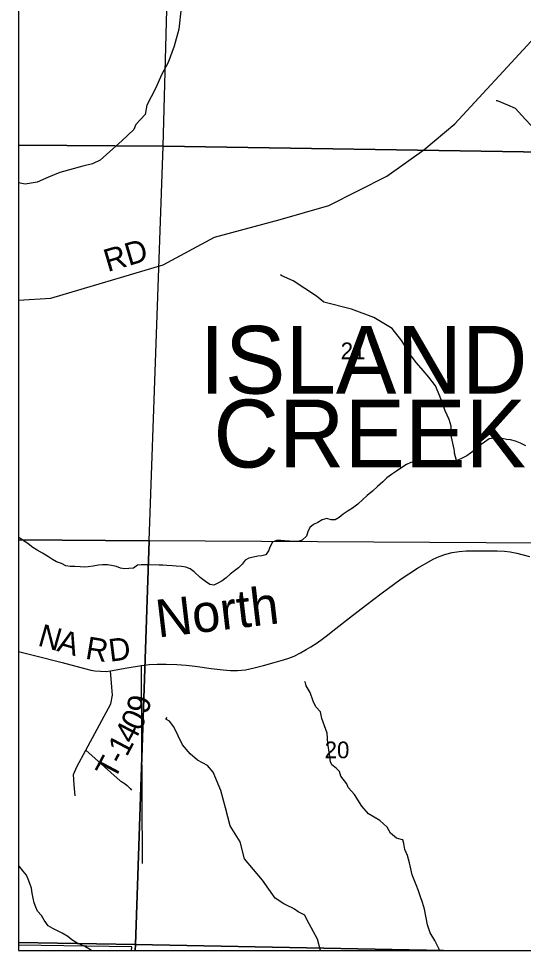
# Model space of a CAD drawing. Extents: x 2.1 to 8.9, y 14.1 to 20.9.
# Drawn here: x 2.1 to 3.368, y 14.1 to 16.441 of the extents above; entities that cross this region are included whole.
import ezdxf

# ---------------------------------------------------------------- set-up
doc = ezdxf.new("R2010")
doc.units = 0
for name, color, linetype in [('Default', 7, 'Continuous'), ('GM_X_City_Street', 7, 'Continuous'), ('GM_X_County_Road_Text', 7, 'Continuous'), ('GM_X_Interchange_Ramps', 7, 'Continuous'), ('GM_X_Minor_River', 7, 'Continuous'), ('GM_X_Minor_River_Text', 7, 'Continuous'), ('GM_X_State_Shield', 7, 'Continuous'), ('GM_X_Township_Road_Text', 7, 'Continuous'), ('PV_P_Text', 7, 'Continuous'), ('SH_Cut_Line', 7, 'Continuous'), ('SH_Data', 7, 'Continuous'), ('TX_P_Misc', 7, 'Continuous')]:
    doc.layers.add(name, color=color, linetype=linetype)

msp = doc.modelspace()

# ---------------------------------------------------------------- linework, layer by layer
at = {"layer": 'Default'}
for p, q in [((2.1, 19.1502), (2.1, 14.1)), ((2.1, 17.1299), (2.1, 16.1234)), ((2.4631, 16.1204), (2.4891, 17.1265)), ((2.1, 16.1234), (2.4631, 16.1204)), ((2.1, 16.1234), (2.1, 15.1312)), ((2.4631, 16.1204), (2.1, 16.1234)), ((2.428, 15.1288), (2.4631, 16.1204)), ((2.1, 15.1312), (2.428, 15.1288)), ((2.1, 15.1312), (2.1, 14.1197)), ((2.428, 15.1288), (2.1, 15.1312)), ((2.3934, 14.1146), (2.428, 15.1288)), ((2.428, 15.1288), (2.3934, 14.1146)), ((3.4148, 15.1232), (2.428, 15.1288)), ((2.1, 14.1197), (2.3934, 14.1146)), ((2.1, 14.1197), (2.1, 14.1)), ((2.3934, 14.1146), (2.1, 14.1197)), ((2.1, 14.1134), (2.1, 14.1)), ((2.384, 14.1091), (2.1, 14.1134)), ((2.1, 14.1), (2.3928, 14.1)), ((2.1, 14.1), (2.3837, 14.1)), ((2.1, 14.1), (6.7017, 14.1)), ((2.3837, 14.1), (2.384, 14.1091)), ((2.3928, 14.1), (2.3934, 14.1146)), ((2.3934, 14.1146), (2.3928, 14.1)), ((2.3928, 14.1), (3.167, 14.1)), ((2.3934, 14.1146), (3.167, 14.1)), ((3.167, 14.1), (2.3934, 14.1146)), ((3.167, 14.1), (3.3681, 14.1))]:
    msp.add_line(p, q, dxfattribs=at)
at = {"layer": 'GM_X_City_Street'}
for p, q in [((2.3337, 14.7617), (2.331, 14.8021)), ((2.4112, 14.3179), (2.4084, 14.8159)), ((2.3361, 14.7414), (2.3337, 14.7617)), ((2.3314, 14.7196), (2.3361, 14.7414)), ((2.269, 14.6027), (2.3314, 14.7196)), ((2.2464, 14.5614), (2.269, 14.6027)), ((2.269, 14.6027), (2.3548, 14.526)), ((2.2379, 14.5419), (2.2464, 14.5614)), ((2.2394, 14.5162), (2.2379, 14.5419)), ((2.2418, 14.4881), (2.2394, 14.5162)), ((2.3548, 14.526), (2.3587, 14.5239)), ((2.3587, 14.5239), (2.3633, 14.5211)), ((2.3633, 14.5211), (2.3677, 14.518)), ((2.3677, 14.518), (2.3723, 14.5144)), ((2.3723, 14.5144), (2.3766, 14.5104)), ((2.3766, 14.5104), (2.3801, 14.5067)), ((2.3801, 14.5067), (2.3836, 14.5026))]:
    msp.add_line(p, q, dxfattribs=at)
at = {"layer": 'GM_X_Interchange_Ramps'}
for p, q in [((2.4631, 16.1204), (2.4891, 17.1265)), ((2.428, 15.1288), (2.4631, 16.1204)), ((3.4577, 16.1051), (2.4631, 16.1204)), ((2.4631, 16.1204), (3.4577, 16.1051)), ((3.4148, 15.1232), (2.428, 15.1288))]:
    msp.add_line(p, q, dxfattribs=at)
at = {"layer": 'GM_X_State_Shield'}
for p, q in [((3.1953, 16.1767), (3.387, 16.3849)), ((3.1174, 16.1114), (3.1953, 16.1767)), ((3.0247, 16.045), (3.1174, 16.1114)), ((2.8794, 15.9713), (3.0247, 16.045)), ((2.7567, 15.9362), (2.8794, 15.9713)), ((2.5919, 15.8922), (2.7567, 15.9362)), ((2.4632, 15.8222), (2.5919, 15.8922)), ((2.1809, 15.7386), (2.4632, 15.8222)), ((2.1, 15.7337), (2.1809, 15.7386)), ((3.1889, 15.0996), (3.2067, 15.1022)), ((3.2067, 15.1022), (3.2243, 15.1035)), ((3.2243, 15.1035), (3.2648, 15.104)), ((3.2648, 15.104), (3.302, 15.1035)), ((3.302, 15.1035), (3.3198, 15.1028)), ((3.3198, 15.1028), (3.3345, 15.1014)), ((3.3345, 15.1014), (3.3509, 15.0983)), ((3.1017, 15.0601), (3.1412, 15.0827)), ((3.1412, 15.0827), (3.1564, 15.09)), ((3.1564, 15.09), (3.1732, 15.0957)), ((3.1732, 15.0957), (3.1889, 15.0996)), ((3.3509, 15.0983), (3.383, 15.0898)), ((3.0609, 15.0334), (3.1017, 15.0601)), ((3.0096, 14.9958), (3.0609, 15.0334)), ((2.9744, 14.9692), (3.0096, 14.9958)), ((2.9381, 14.9413), (2.9744, 14.9692)), ((2.8893, 14.9028), (2.9381, 14.9413)), ((2.8622, 14.882), (2.8759, 14.8919)), ((2.8759, 14.8919), (2.8893, 14.9028)), ((2.8337, 14.8626), (2.8496, 14.8729)), ((2.8496, 14.8729), (2.8622, 14.882)), ((2.1, 14.8512), (2.1395, 14.8412)), ((2.7918, 14.8395), (2.8075, 14.8472)), ((2.8075, 14.8472), (2.8224, 14.8556)), ((2.8224, 14.8556), (2.8337, 14.8626)), ((2.1395, 14.8412), (2.2097, 14.8229)), ((2.2097, 14.8229), (2.2686, 14.807)), ((2.7147, 14.8154), (2.7416, 14.8229)), ((2.7416, 14.8229), (2.7652, 14.8297)), ((2.7652, 14.8297), (2.7787, 14.8341)), ((2.7787, 14.8341), (2.7918, 14.8395)), ((2.2686, 14.807), (2.2813, 14.8041)), ((2.2813, 14.8041), (2.2916, 14.8027)), ((2.2916, 14.8027), (2.3058, 14.8013)), ((2.3058, 14.8013), (2.3196, 14.8008)), ((2.3196, 14.8008), (2.331, 14.8021)), ((2.331, 14.8021), (2.3723, 14.8099)), ((2.3723, 14.8099), (2.4084, 14.8159)), ((2.4084, 14.8159), (2.4279, 14.8179)), ((2.4279, 14.8179), (2.4481, 14.8187)), ((2.4481, 14.8187), (2.4705, 14.8188)), ((2.4705, 14.8188), (2.4973, 14.8182)), ((2.4973, 14.8182), (2.5208, 14.8163)), ((2.5208, 14.8163), (2.5432, 14.8137)), ((2.5432, 14.8137), (2.5832, 14.8084)), ((2.5832, 14.8084), (2.6136, 14.805)), ((2.6136, 14.805), (2.6323, 14.8034)), ((2.6323, 14.8034), (2.6497, 14.8031)), ((2.6497, 14.8031), (2.6698, 14.8052)), ((2.6698, 14.8052), (2.6913, 14.8097)), ((2.6913, 14.8097), (2.7147, 14.8154))]:
    msp.add_line(p, q, dxfattribs=at)
at = {"layer": 'SH_Cut_Line'}
for p, q in [((2.1, 20.9), (2.1, 14.1)), ((2.1, 14.1), (6.7017, 14.1))]:
    msp.add_line(p, q, dxfattribs=at)
at = {"layer": 'SH_Data'}
for p, q in [((2.1, 20.9), (2.1, 14.1)), ((2.1, 20.9), (2.1, 14.1)), ((2.1, 14.1), (8.9, 14.1)), ((2.1, 14.1), (2.1, 14.1)), ((2.1, 14.1), (8.9, 14.1)), ((2.1, 14.1), (2.1, 14.1))]:
    msp.add_line(p, q, dxfattribs=at)
at = {"layer": 'TX_P_Misc'}
for p, q in [((2.5085, 16.4686), (2.5023, 16.4145)), ((2.5023, 16.4145), (2.4906, 16.3724)), ((2.4906, 16.3724), (2.4754, 16.3311)), ((2.4754, 16.3311), (2.46, 16.3016)), ((2.46, 16.3016), (2.4436, 16.2659)), ((2.4436, 16.2659), (2.4217, 16.2237)), ((3.3027, 16.235), (3.2993, 16.2349)), ((3.3282, 16.224), (3.3027, 16.235)), ((2.4217, 16.2237), (2.4179, 16.2001)), ((3.348, 16.2155), (3.3282, 16.224)), ((3.3638, 16.1979), (3.348, 16.2155)), ((2.4179, 16.2001), (2.3946, 16.1749)), ((3.3954, 16.1631), (3.3638, 16.1979)), ((2.3891, 16.1623), (2.3594, 16.134)), ((2.3946, 16.1749), (2.3891, 16.1623)), ((2.3594, 16.134), (2.3366, 16.1139)), ((2.3366, 16.1139), (2.305, 16.0852)), ((2.305, 16.0852), (2.2851, 16.0765)), ((2.261, 16.0704), (2.2031, 16.0546)), ((2.2851, 16.0765), (2.261, 16.0704)), ((2.175, 16.0427), (2.1464, 16.0301)), ((2.2031, 16.0546), (2.175, 16.0427)), ((2.1163, 16.0254), (2.1, 16.0289)), ((2.1464, 16.0301), (2.1163, 16.0254)), ((2.7611, 15.7947), (2.7577, 15.7973)), ((2.7893, 15.7822), (2.7611, 15.7947)), ((2.8482, 15.7437), (2.7893, 15.7822)), ((2.8662, 15.7284), (2.8482, 15.7437)), ((2.9357, 15.7109), (2.8662, 15.7284)), ((2.9924, 15.6898), (2.9357, 15.7109)), ((3.0379, 15.6624), (2.9924, 15.6898)), ((3.0623, 15.6316), (3.0379, 15.6624)), ((3.0829, 15.5974), (3.0623, 15.6316)), ((3.0991, 15.5764), (3.0829, 15.5974)), ((3.1157, 15.5569), (3.0991, 15.5764)), ((3.1304, 15.54), (3.1157, 15.5569)), ((3.1467, 15.5182), (3.1304, 15.54)), ((3.1577, 15.4926), (3.1467, 15.5182)), ((3.1712, 15.4555), (3.1577, 15.4926)), ((3.1814, 15.4336), (3.1712, 15.4555)), ((3.1859, 15.4174), (3.1814, 15.4336)), ((3.1875, 15.3893), (3.1859, 15.4174)), ((3.1937, 15.3593), (3.1875, 15.3893)), ((3.2821, 15.385), (3.2698, 15.377)), ((3.2934, 15.3872), (3.2821, 15.385)), ((3.304, 15.3876), (3.2934, 15.3872)), ((3.3147, 15.386), (3.304, 15.3876)), ((3.3254, 15.384), (3.3147, 15.386)), ((3.335, 15.3828), (3.3254, 15.384)), ((3.3476, 15.3798), (3.335, 15.3828)), ((3.1945, 15.3544), (3.1937, 15.3593)), ((3.2594, 15.369), (3.2464, 15.358)), ((3.2698, 15.377), (3.2594, 15.369)), ((3.3607, 15.3745), (3.3476, 15.3798)), ((3.3735, 15.368), (3.3607, 15.3745)), ((3.1946, 15.3495), (3.1945, 15.3544)), ((3.1999, 15.3306), (3.1946, 15.3495)), ((3.214, 15.3364), (3.2031, 15.3315)), ((3.2252, 15.3425), (3.214, 15.3364)), ((3.2349, 15.3489), (3.2252, 15.3425)), ((3.2464, 15.358), (3.2349, 15.3489)), ((3.0623, 15.3131), (3.0492, 15.3043)), ((3.0738, 15.3206), (3.0623, 15.3131)), ((3.0851, 15.3256), (3.0738, 15.3206)), ((3.0964, 15.3278), (3.0851, 15.3256)), ((3.1063, 15.3285), (3.0964, 15.3278)), ((3.1158, 15.3288), (3.1063, 15.3285)), ((3.1257, 15.3284), (3.1158, 15.3288)), ((3.1382, 15.3272), (3.1257, 15.3284)), ((3.1527, 15.3258), (3.1382, 15.3272)), ((3.1672, 15.3255), (3.1527, 15.3258)), ((3.1809, 15.3259), (3.1672, 15.3255)), ((3.1911, 15.3281), (3.1809, 15.3259)), ((3.2031, 15.3315), (3.1911, 15.3281)), ((3.0362, 15.2959), (3.0251, 15.2872)), ((3.0492, 15.3043), (3.0362, 15.2959)), ((3.0014, 15.2659), (2.9885, 15.2541)), ((3.0144, 15.2769), (3.0014, 15.2659)), ((3.0251, 15.2872), (3.0144, 15.2769)), ((2.9755, 15.243), (2.9648, 15.2328)), ((2.9885, 15.2541), (2.9755, 15.243)), ((2.9518, 15.2214), (2.9381, 15.211)), ((2.9648, 15.2328), (2.9518, 15.2214)), ((2.9154, 15.1959), (2.9054, 15.1876)), ((2.928, 15.2046), (2.9154, 15.1959)), ((2.9381, 15.211), (2.928, 15.2046)), ((2.8514, 15.1752), (2.8409, 15.17)), ((2.8626, 15.1821), (2.8514, 15.1752)), ((2.8739, 15.1854), (2.8626, 15.1821)), ((2.8846, 15.182), (2.8739, 15.1854)), ((2.8949, 15.1815), (2.8846, 15.182)), ((2.9054, 15.1876), (2.8949, 15.1815)), ((2.8267, 15.1516), (2.8232, 15.1405)), ((2.8312, 15.1628), (2.8267, 15.1516)), ((2.8409, 15.17), (2.8312, 15.1628)), ((2.1029, 15.1361), (2.1, 15.1388)), ((2.1134, 15.1288), (2.1029, 15.1361)), ((2.1242, 15.1212), (2.1134, 15.1288)), ((2.7377, 15.1257), (2.732, 15.1148)), ((2.7479, 15.1302), (2.7377, 15.1257)), ((2.7581, 15.1297), (2.7479, 15.1302)), ((2.7677, 15.1289), (2.7581, 15.1297)), ((2.7806, 15.1278), (2.7677, 15.1289)), ((2.7917, 15.127), (2.7806, 15.1278)), ((2.8012, 15.1273), (2.7917, 15.127)), ((2.8121, 15.131), (2.8012, 15.1273)), ((2.8232, 15.1405), (2.8121, 15.131)), ((2.1355, 15.1124), (2.1242, 15.1212)), ((2.1468, 15.1055), (2.1355, 15.1124)), ((2.1596, 15.0983), (2.1468, 15.1055)), ((2.7274, 15.1037), (2.7209, 15.0936)), ((2.732, 15.1148), (2.7274, 15.1037)), ((2.1747, 15.0885), (2.1596, 15.0983)), ((2.1852, 15.082), (2.1747, 15.0885)), ((2.1952, 15.0766), (2.1852, 15.082)), ((2.6688, 15.0805), (2.6615, 15.0708)), ((2.6785, 15.0858), (2.6688, 15.0805)), ((2.6902, 15.0884), (2.6785, 15.0858)), ((2.7008, 15.0906), (2.6902, 15.0884)), ((2.7111, 15.0917), (2.7008, 15.0906)), ((2.7209, 15.0936), (2.7111, 15.0917)), ((2.2075, 15.0717), (2.1952, 15.0766)), ((2.2187, 15.0664), (2.2075, 15.0717)), ((2.229, 15.0648), (2.2187, 15.0664)), ((2.2412, 15.0644), (2.229, 15.0648)), ((2.2545, 15.0637), (2.2412, 15.0644)), ((2.2648, 15.0632), (2.2545, 15.0637)), ((2.2747, 15.0636), (2.2648, 15.0632)), ((2.2872, 15.0655), (2.2747, 15.0636)), ((2.3004, 15.0678), (2.2872, 15.0655)), ((2.311, 15.0689), (2.3004, 15.0678)), ((2.3232, 15.0689), (2.311, 15.0689)), ((2.3331, 15.0673), (2.3232, 15.0689)), ((2.3454, 15.0646), (2.3331, 15.0673)), ((2.3558, 15.0604), (2.3454, 15.0646)), ((2.3661, 15.0584), (2.3558, 15.0604)), ((2.3764, 15.0591), (2.3661, 15.0584)), ((2.3885, 15.0607), (2.3764, 15.0591)), ((2.3985, 15.0678), (2.3885, 15.0607)), ((2.408, 15.0685), (2.3985, 15.0678)), ((2.4175, 15.0684), (2.408, 15.0685)), ((2.4274, 15.0687), (2.4175, 15.0684)), ((2.4525, 15.068), (2.4274, 15.0687)), ((2.4624, 15.0676), (2.4525, 15.068)), ((2.4723, 15.0667), (2.4624, 15.0676)), ((2.486, 15.066), (2.4723, 15.0667)), ((2.4955, 15.0652), (2.486, 15.066)), ((2.5092, 15.0649), (2.4955, 15.0652)), ((2.52, 15.0625), (2.5092, 15.0649)), ((2.5304, 15.0587), (2.52, 15.0625)), ((2.5412, 15.0514), (2.5304, 15.0587)), ((2.6519, 15.0614), (2.6423, 15.0538)), ((2.6615, 15.0708), (2.6519, 15.0614)), ((2.5561, 15.037), (2.5412, 15.0514)), ((2.569, 15.0268), (2.5561, 15.037)), ((2.6212, 15.036), (2.6108, 15.0281)), ((2.6315, 15.0455), (2.6212, 15.036)), ((2.6423, 15.0538), (2.6315, 15.0455)), ((2.5799, 15.0195), (2.569, 15.0268)), ((2.5898, 15.018), (2.5799, 15.0195)), ((2.5999, 15.0225), (2.5898, 15.018)), ((2.6108, 15.0281), (2.5999, 15.0225)), ((2.8204, 14.7723), (2.8189, 14.7757)), ((2.8221, 14.7644), (2.8204, 14.7723)), ((2.8322, 14.7478), (2.8221, 14.7644)), ((2.8398, 14.7259), (2.8322, 14.7478)), ((2.8461, 14.712), (2.8398, 14.7259)), ((2.858, 14.6996), (2.8461, 14.712)), ((2.4697, 14.681), (2.4727, 14.6848)), ((2.4785, 14.6758), (2.4697, 14.681)), ((2.8617, 14.6826), (2.858, 14.6996)), ((2.8748, 14.6459), (2.8617, 14.6826)), ((2.4894, 14.6619), (2.4785, 14.6758)), ((2.5113, 14.6163), (2.4894, 14.6619)), ((2.8768, 14.6197), (2.8748, 14.6459)), ((2.531, 14.5942), (2.5113, 14.6163)), ((2.8807, 14.5932), (2.8768, 14.6197)), ((2.5491, 14.5778), (2.531, 14.5942)), ((2.8833, 14.5739), (2.8807, 14.5932)), ((2.5746, 14.5642), (2.5491, 14.5778)), ((2.5889, 14.5477), (2.5746, 14.5642)), ((2.8865, 14.5663), (2.8833, 14.5739)), ((2.8976, 14.5574), (2.8865, 14.5663)), ((2.6079, 14.5016), (2.5889, 14.5477)), ((2.906, 14.5495), (2.8976, 14.5574)), ((2.9093, 14.5378), (2.906, 14.5495)), ((2.9244, 14.5187), (2.9093, 14.5378)), ((2.9276, 14.5096), (2.9244, 14.5187)), ((2.6192, 14.4581), (2.6079, 14.5016)), ((2.9437, 14.4916), (2.9276, 14.5096)), ((2.962, 14.4627), (2.9437, 14.4916)), ((2.631, 14.4131), (2.6192, 14.4581)), ((2.979, 14.4432), (2.962, 14.4627)), ((3.0073, 14.4262), (2.979, 14.4432)), ((3.0257, 14.4098), (3.0073, 14.4262)), ((2.6567, 14.3725), (2.631, 14.4131)), ((3.0336, 14.3943), (3.0257, 14.4098)), ((3.0489, 14.382), (3.0336, 14.3943)), ((3.0607, 14.3784), (3.0489, 14.382)), ((3.0649, 14.3777), (3.0607, 14.3784)), ((3.0677, 14.3686), (3.0649, 14.3777)), ((2.6669, 14.3301), (2.6567, 14.3725)), ((3.0702, 14.3535), (3.0677, 14.3686)), ((3.0769, 14.338), (3.0702, 14.3535)), ((2.7125, 14.2765), (2.6669, 14.3301)), ((3.0818, 14.3202), (3.0769, 14.338)), ((2.1018, 14.3106), (2.1, 14.3128)), ((2.1113, 14.2987), (2.1018, 14.3106)), ((3.0887, 14.2899), (3.0818, 14.3202)), ((2.1196, 14.2891), (2.1113, 14.2987)), ((2.1237, 14.2786), (2.1196, 14.2891)), ((3.0986, 14.265), (3.0887, 14.2899)), ((2.1278, 14.2677), (2.1237, 14.2786)), ((2.132, 14.2564), (2.1278, 14.2677)), ((2.7446, 14.2314), (2.7125, 14.2765)), ((3.1046, 14.2499), (3.0986, 14.265)), ((2.1343, 14.2436), (2.132, 14.2564)), ((2.1366, 14.2311), (2.1343, 14.2436)), ((3.109, 14.2348), (3.1046, 14.2499)), ((3.1145, 14.2201), (3.109, 14.2348)), ((2.1392, 14.2194), (2.1366, 14.2311)), ((2.143, 14.2081), (2.1392, 14.2194)), ((2.7664, 14.217), (2.7446, 14.2314)), ((2.779, 14.2103), (2.7664, 14.217)), ((3.1194, 14.2038), (3.1145, 14.2201)), ((2.1475, 14.1983), (2.143, 14.2081)), ((2.157, 14.1876), (2.1475, 14.1983)), ((2.7851, 14.2074), (2.779, 14.2103)), ((2.7924, 14.2033), (2.7851, 14.2074)), ((2.802, 14.1966), (2.7924, 14.2033)), ((2.8191, 14.1882), (2.802, 14.1966)), ((2.825, 14.1757), (2.8191, 14.1882)), ((3.1269, 14.1644), (3.1194, 14.2038)), ((2.1642, 14.1761), (2.157, 14.1876)), ((2.1745, 14.1616), (2.1642, 14.1761)), ((2.8508, 14.1283), (2.825, 14.1757)), ((2.1861, 14.1547), (2.1745, 14.1616)), ((2.1973, 14.1493), (2.1861, 14.1547)), ((2.2093, 14.1433), (2.1973, 14.1493)), ((2.2236, 14.135), (2.2093, 14.1433)), ((3.1333, 14.1436), (3.1269, 14.1644)), ((3.145, 14.1244), (3.1333, 14.1436)), ((2.2338, 14.1265), (2.2236, 14.135)), ((2.2443, 14.12), (2.2338, 14.1265)), ((2.2551, 14.115), (2.2443, 14.12)), ((2.8584, 14.1), (2.8508, 14.1283)), ((3.1559, 14.1033), (3.145, 14.1244)), ((2.2659, 14.1093), (2.2551, 14.115)), ((2.2759, 14.1039), (2.2659, 14.1093)), ((2.283, 14.1), (2.2759, 14.1039)), ((3.1573, 14.1), (3.1559, 14.1033))]:
    msp.add_line(p, q, dxfattribs=at)

# ---------------------------------------------------------------- texts
at = {"layer": 'GM_X_County_Road_Text'}
for s, p in [('21', (2.9088, 15.5855)), ('20', (2.8684, 14.5827))]:
    msp.add_text(s, height=0.04186, rotation=0, dxfattribs=at).set_placement(p)
at = {"layer": 'GM_X_Minor_River'}
for s, height, rotation, p in [('RD', 0.05682, 16.4177, (2.3237, 15.8041)), ('N', 0.0568, 344.1762, (2.1456, 14.8665)), ('A', 0.0568, 344.1846, (2.1938, 14.8528)), ('R', 0.0568, 350.5919, (2.2655, 14.833)), ('D', 0.0568, 7.2488, (2.3295, 14.8251))]:
    msp.add_text(s, height=height, rotation=rotation, dxfattribs=at).set_placement(p)
at = {"layer": 'GM_X_Minor_River_Text'}
for s, rotation, p in [('9', 75.8528, (2.4246, 14.6918)), ('0', 64.0846, (2.405, 14.6484)), ('4', 62.612, (2.3881, 14.6159)), ('1', 62.0795, (2.3715, 14.5845)), ('T', 61.892, (2.3404, 14.5262)), ('-', 61.9157, (2.3604, 14.5637))]:
    msp.add_text(s, height=0.0568, rotation=rotation, dxfattribs=at).set_placement(p)
at = {"layer": 'GM_X_Township_Road_Text'}
for s, p in [('ISLAND', (2.5546, 15.4988)), ('CREEK', (2.5892, 15.3133))]:
    msp.add_text(s, height=0.17045, rotation=0, dxfattribs=at).set_placement(p)
at = {"layer": 'PV_P_Text'}
msp.add_text('North', height=0.09471, rotation=6.7071, dxfattribs=at).set_placement((2.4498, 14.8858))

doc.saveas('drawing.dxf')
